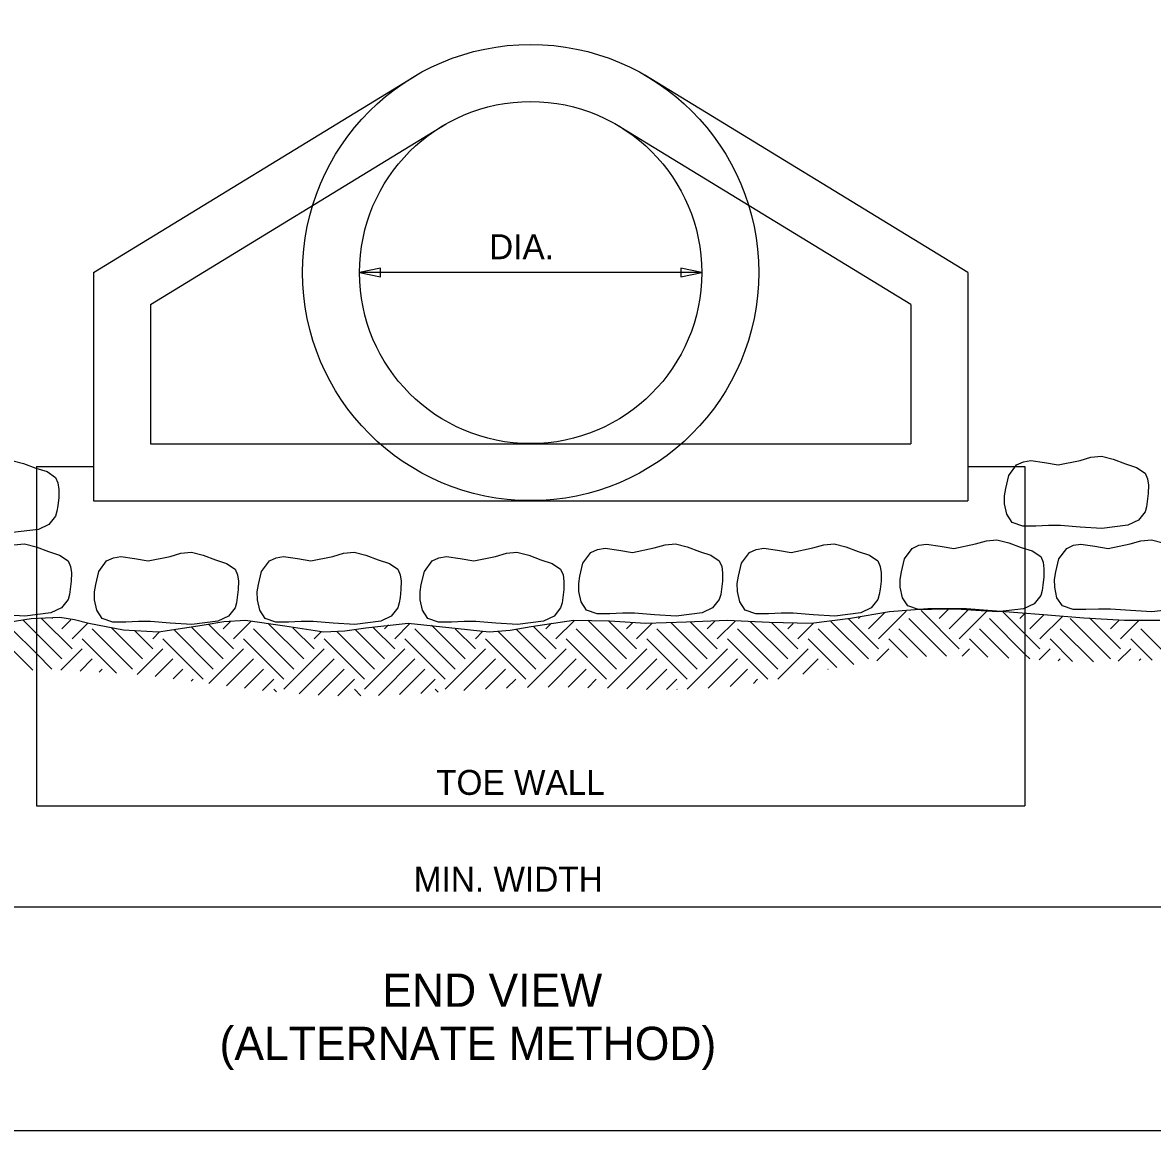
# Model space of a CAD drawing. Extents: x -439.1 to -407.9, y -458.1 to -436.2.
# Drawn here: x -431.65 to -424.86, y -458.05 to -451.39 of the extents above; entities that cross this region are included whole.
import ezdxf

# ---------------------------------------------------------------- set-up
doc = ezdxf.new("R2010")
doc.units = 0
doc.layers.add('Draft_Named_Boundary', color=7, linetype='Continuous')
doc.layers.add('Level 4', color=7, linetype='Continuous')

msp = doc.modelspace()

# ---------------------------------------------------------------- linework, layer by layer
at = {"layer": 'Draft_Named_Boundary'}
msp.add_lwpolyline([(-439.109, -458.0508), (-407.859, -458.0508), (-407.859, -437.6758), (-439.109, -437.6758)], close=True, dxfattribs=at)
at = {"layer": 'Level 4'}
for p, q in [((-431.2258, -452.893), (-429.2828, -451.7055)), ((-425.9682, -452.893), (-427.9112, -451.7055)), ((-430.8829, -453.0851), (-429.1045, -451.9981)), ((-426.3111, -453.0851), (-428.0907, -451.9981)), ((-431.2258, -452.893), (-431.2258, -454.2646)), ((-427.5687, -452.8928), (-429.626, -452.8928)), ((-425.9682, -452.893), (-425.9682, -454.2646)), ((-430.8829, -453.0851), (-430.8829, -453.9217)), ((-426.3111, -453.0851), (-426.3111, -453.9217)), ((-430.8829, -453.9217), (-426.3111, -453.9217)), ((-431.5687, -454.0588), (-431.2258, -454.0588)), ((-431.5687, -454.0588), (-431.5687, -456.1002)), ((-425.9682, -454.0588), (-425.6253, -454.0588)), ((-425.6253, -454.0588), (-425.6253, -456.1002)), ((-431.2258, -454.2646), (-425.9682, -454.2646)), ((-426.5659, -455.0344), (-426.4685, -454.9371)), ((-426.5053, -455.0951), (-426.339, -454.9288)), ((-426.0204, -455.1557), (-426.2505, -454.9256)), ((-426.1416, -454.9738), (-426.0874, -454.9196)), ((-426.081, -455.0344), (-425.9632, -454.9167)), ((-426.0204, -455.0951), (-425.8504, -454.925)), ((-425.6256, -455.0655), (-425.7594, -454.9318)), ((-425.6567, -454.9738), (-425.6256, -454.9428)), ((-425.6256, -454.9428), (-425.6246, -454.9417)), ((-425.5961, -455.0344), (-425.5117, -454.9501)), ((-425.5355, -455.0951), (-425.3986, -454.9582)), ((-431.569, -455.0623), (-431.6491, -454.9822)), ((-431.3544, -455.1557), (-431.5381, -454.972)), ((-431.4757, -454.9738), (-431.471, -454.9691)), ((-431.415, -455.0344), (-431.3612, -454.9806)), ((-431.3544, -455.0951), (-431.2602, -455.0008)), ((-430.4452, -455.2163), (-430.6353, -455.0262)), ((-430.3846, -455.1557), (-430.5334, -455.0069)), ((-430.4452, -455.0344), (-430.3993, -454.9886)), ((-430.3846, -455.0951), (-430.2777, -454.9882)), ((-429.9603, -455.2163), (-430.1766, -455)), ((-429.4148, -455.1557), (-429.5462, -455.0242)), ((-429.4754, -455.0344), (-429.4516, -455.0106)), ((-429.4148, -455.0951), (-429.3227, -455.003)), ((-428.9905, -455.2163), (-429.1937, -455.013)), ((-428.4449, -455.1557), (-428.5794, -455.0213)), ((-428.5056, -455.0344), (-428.4727, -455.0015)), ((-428.445, -455.0951), (-428.3346, -454.9847)), ((-428.0207, -455.2163), (-428.2537, -454.9832)), ((-427.96, -455.1557), (-428.1274, -454.9883)), ((-428.0207, -455.0344), (-427.9844, -454.9981)), ((-427.96, -455.0951), (-427.8668, -455.0018)), ((-427.5357, -455.2163), (-427.7527, -454.9994)), ((-427.4751, -455.1557), (-427.6376, -454.9932)), ((-427.5357, -455.0344), (-427.4877, -454.9864)), ((-427.4751, -455.0951), (-427.3666, -454.9865)), ((-427.0508, -455.2163), (-427.2771, -454.99)), ((-426.9902, -455.1557), (-427.1478, -454.9981)), ((-427.0508, -455.0344), (-427.0198, -455.0034)), ((-426.9902, -455.0951), (-426.896, -455.0008)), ((-426.5659, -455.2163), (-426.7917, -454.9905)), ((-426.5053, -455.1557), (-426.6871, -454.9739)), ((-426.6265, -454.9738), (-426.6138, -454.9611)), ((-426.098, -455.1993), (-426.3235, -454.9738)), ((-425.6256, -455.1867), (-425.8385, -454.9738)), ((-425.1112, -455.2163), (-425.3536, -454.9738)), ((-425.0506, -455.1557), (-425.2365, -454.9697)), ((-425.1112, -455.0344), (-425.0591, -454.9824)), ((-425.0506, -455.0951), (-424.9405, -454.985)), ((-431.569, -455.1836), (-431.7181, -455.0344)), ((-431.415, -455.2163), (-431.569, -455.0623)), ((-430.9907, -455.2769), (-431.2332, -455.0344)), ((-430.9301, -455.2163), (-431.1169, -455.0295)), ((-430.8695, -455.1557), (-430.9778, -455.0473)), ((-430.8695, -455.0951), (-430.8283, -455.0538)), ((-430.5058, -455.2769), (-430.7387, -455.044)), ((-430.0209, -455.2769), (-430.2634, -455.0344)), ((-429.8997, -455.1557), (-430.0265, -455.0289)), ((-429.8997, -455.0951), (-429.8574, -455.0527)), ((-429.536, -455.2769), (-429.762, -455.0509)), ((-429.4754, -455.2163), (-429.6519, -455.0398)), ((-429.0511, -455.2769), (-429.2935, -455.0344)), ((-428.9299, -455.1557), (-429.0515, -455.0341)), ((-428.9299, -455.0951), (-428.8866, -455.0518)), ((-428.5662, -455.2769), (-428.7925, -455.0505)), ((-428.5056, -455.2163), (-428.6829, -455.0389)), ((-428.0813, -455.2769), (-428.3237, -455.0344)), ((-427.5964, -455.2769), (-427.8388, -455.0344)), ((-427.1114, -455.2769), (-427.3539, -455.0344)), ((-426.6542, -455.2492), (-426.869, -455.0344)), ((-426.2175, -455.201), (-426.3841, -455.0344)), ((-425.7221, -455.2115), (-425.8992, -455.0344)), ((-425.5355, -455.1557), (-425.6256, -455.0655)), ((-425.2143, -455.2344), (-425.4142, -455.0344)), ((-424.7441, -455.2197), (-424.9293, -455.0344)), ((-431.5897, -455.284), (-431.7787, -455.0951)), ((-431.4217, -455.2836), (-431.2938, -455.1557)), ((-431.0866, -455.3023), (-431.2938, -455.0951)), ((-430.9632, -455.31), (-430.8089, -455.1557)), ((-430.5664, -455.3375), (-430.8089, -455.0951)), ((-430.5321, -455.3638), (-430.324, -455.1557)), ((-430.0815, -455.3375), (-430.324, -455.0951)), ((-430.0815, -455.3981), (-429.8391, -455.1557)), ((-429.5966, -455.3375), (-429.8391, -455.0951)), ((-429.5966, -455.3981), (-429.3542, -455.1557)), ((-429.1117, -455.3375), (-429.3542, -455.0951)), ((-429.1117, -455.3981), (-428.8692, -455.1557)), ((-428.6268, -455.3375), (-428.8692, -455.0951)), ((-428.6165, -455.3878), (-428.3843, -455.1557)), ((-428.1419, -455.3375), (-428.3843, -455.0951)), ((-428.1361, -455.3924), (-427.8994, -455.1557)), ((-427.657, -455.3375), (-427.8994, -455.0951)), ((-427.657, -455.3981), (-427.4145, -455.1557)), ((-427.1721, -455.3375), (-427.4145, -455.0951)), ((-427.1113, -455.3374), (-426.9296, -455.1557)), ((-426.7569, -455.2678), (-426.9296, -455.0951)), ((-426.5161, -455.2271), (-426.4447, -455.1557)), ((-426.3325, -455.2073), (-426.4447, -455.0951)), ((-426.0036, -455.1995), (-425.9598, -455.1557)), ((-425.8497, -455.2051), (-425.9598, -455.0951)), ((-425.5408, -455.2216), (-425.4749, -455.1557)), ((-425.3391, -455.2308), (-425.4749, -455.0951)), ((-425.0642, -455.2299), (-424.99, -455.1557)), ((-424.8613, -455.2237), (-424.99, -455.0951)), ((-431.4757, -455.2769), (-431.569, -455.1836)), ((-431.3056, -455.2887), (-431.2332, -455.2163)), ((-430.8543, -455.3223), (-430.7483, -455.2163)), ((-430.4256, -455.3785), (-430.2634, -455.2163)), ((-429.9889, -455.4268), (-429.7785, -455.2163)), ((-429.5124, -455.4351), (-429.2935, -455.2163)), ((-428.9988, -455.4064), (-428.8086, -455.2163)), ((-428.4927, -455.3852), (-428.3237, -455.2163)), ((-428.0186, -455.396), (-427.8388, -455.2163)), ((-427.5299, -455.3923), (-427.3539, -455.2163)), ((-426.9609, -455.3082), (-426.869, -455.2163)), ((-425.5961, -455.2163), (-425.6256, -455.1867)), ((-425.4258, -455.2278), (-425.4142, -455.2163)), ((-424.9391, -455.2261), (-424.9293, -455.2163)), ((-431.1915, -455.2958), (-431.1726, -455.2769)), ((-430.746, -455.3352), (-430.6877, -455.2769)), ((-430.3182, -455.3924), (-430.2028, -455.2769)), ((-429.8753, -455.4343), (-429.7178, -455.2769)), ((-429.3858, -455.4298), (-429.2329, -455.2769)), ((-428.8695, -455.3984), (-428.748, -455.2769)), ((-428.3726, -455.3864), (-428.2631, -455.2769)), ((-427.9001, -455.3988), (-427.7782, -455.2769)), ((-427.3978, -455.3814), (-427.2933, -455.2769)), ((-426.8097, -455.2782), (-426.8084, -455.2769)), ((-430.6389, -455.3494), (-430.6271, -455.3375)), ((-430.2104, -455.4057), (-430.1421, -455.3375)), ((-429.7569, -455.4371), (-429.6572, -455.3375)), ((-429.2578, -455.423), (-429.1723, -455.3375)), ((-428.7418, -455.3919), (-428.6874, -455.3375)), ((-428.2539, -455.3889), (-428.2025, -455.3375)), ((-427.7806, -455.4005), (-427.7176, -455.3375)), ((-427.2582, -455.363), (-427.2327, -455.3375)), ((-430.1257, -455.4146), (-430.1421, -455.3981)), ((-429.6178, -455.4376), (-429.6572, -455.3981)), ((-429.1541, -455.4164), (-429.1723, -455.3981)), ((-427.7163, -455.3994), (-427.7176, -455.3981)), ((-431.5687, -456.1002), (-425.6253, -456.1002)), ((-421.7848, -456.7088), (-435.0842, -456.7088))]:
    msp.add_line(p, q, dxfattribs=at)
for points in [[(-429.4995, -452.8666), (-429.626, -452.8928), (-429.4995, -452.9191)], [(-427.6951, -452.9191), (-427.5687, -452.8928), (-427.6951, -452.8666)], [(-425.7413, -454.1911), (-425.723, -454.1124), (-425.6756, -454.0498), (-425.6352, -454.0302), (-425.5902, -454.0235), (-425.5074, -454.0358), (-425.4259, -454.0498), (-425.2946, -454.0219), (-425.2296, -454.003), (-425.1663, -453.9972), (-425.0957, -454.0152), (-425.0217, -454.0432), (-424.9546, -454.0641), (-424.9034, -454.0991), (-424.8891, -454.1327), (-424.8837, -454.1713), (-424.8847, -454.221), (-424.8903, -454.2699), (-424.8951, -454.3021), (-424.9034, -454.3324), (-424.9434, -454.3823), (-425.0068, -454.4123), (-425.163, -454.4309), (-425.293, -454.4237), (-425.4127, -454.4145), (-425.4845, -454.4146), (-425.5606, -454.4178), (-425.6377, -454.4178), (-425.7019, -454.3948), (-425.7341, -454.3458), (-425.7479, -454.2831), (-425.7487, -454.2362), (-425.7413, -454.1911)], [(-428.3011, -454.7181), (-428.2828, -454.6395), (-428.2354, -454.5768), (-428.195, -454.5572), (-428.15, -454.5505), (-428.0672, -454.5628), (-427.9857, -454.5768), (-427.8544, -454.5489), (-427.7894, -454.5301), (-427.7261, -454.5242), (-427.6555, -454.5422), (-427.5815, -454.5702), (-427.5144, -454.5911), (-427.4632, -454.6261), (-427.4488, -454.6597), (-427.4435, -454.6984), (-427.4445, -454.748), (-427.4501, -454.7969), (-427.4549, -454.8292), (-427.4632, -454.8594), (-427.5032, -454.9093), (-427.5666, -454.9393), (-427.7228, -454.9579), (-427.8528, -454.9507), (-427.9725, -454.9415), (-428.0442, -454.9416), (-428.1204, -454.9448), (-428.1975, -454.9448), (-428.2617, -454.9218), (-428.2939, -454.8728), (-428.3077, -454.8101), (-428.3085, -454.7632), (-428.3011, -454.7181)], [(-427.3475, -454.7181), (-427.3291, -454.6395), (-427.2818, -454.5768), (-427.2414, -454.5572), (-427.1963, -454.5505), (-427.1135, -454.5628), (-427.032, -454.5768), (-426.9007, -454.5489), (-426.8357, -454.5301), (-426.7724, -454.5242), (-426.7019, -454.5422), (-426.6279, -454.5702), (-426.5607, -454.5911), (-426.5096, -454.6261), (-426.4952, -454.6597), (-426.4899, -454.6984), (-426.4909, -454.748), (-426.4964, -454.7969), (-426.5012, -454.8292), (-426.5096, -454.8594), (-426.5495, -454.9093), (-426.613, -454.9393), (-426.7692, -454.9579), (-426.8991, -454.9507), (-427.0189, -454.9415), (-427.0906, -454.9416), (-427.1668, -454.9448), (-427.2439, -454.9448), (-427.308, -454.9218), (-427.3403, -454.8728), (-427.354, -454.8101), (-427.3548, -454.7632), (-427.3475, -454.7181)], [(-426.3687, -454.693), (-426.3504, -454.6144), (-426.303, -454.5517), (-426.2626, -454.5321), (-426.2176, -454.5254), (-426.1348, -454.5377), (-426.0533, -454.5517), (-425.922, -454.5238), (-425.857, -454.505), (-425.7937, -454.4991), (-425.7231, -454.5171), (-425.6491, -454.5451), (-425.582, -454.566), (-425.5308, -454.601), (-425.5164, -454.6346), (-425.5111, -454.6733), (-425.5121, -454.7229), (-425.5177, -454.7718), (-425.5225, -454.8041), (-425.5308, -454.8343), (-425.5708, -454.8842), (-425.6342, -454.9142), (-425.7904, -454.9328), (-425.9204, -454.9256), (-426.0401, -454.9164), (-426.1119, -454.9165), (-426.188, -454.9197), (-426.2651, -454.9197), (-426.3293, -454.8967), (-426.3615, -454.8477), (-426.3753, -454.785), (-426.3761, -454.7381), (-426.3687, -454.693)], [(-431.2123, -454.7683), (-431.1939, -454.6897), (-431.1465, -454.627), (-431.1061, -454.6074), (-431.0611, -454.6007), (-430.9783, -454.613), (-430.8968, -454.627), (-430.7655, -454.5991), (-430.7005, -454.5803), (-430.6372, -454.5744), (-430.5666, -454.5924), (-430.4927, -454.6204), (-430.4255, -454.6413), (-430.3744, -454.6763), (-430.36, -454.7099), (-430.3546, -454.7486), (-430.3556, -454.7982), (-430.3612, -454.8471), (-430.366, -454.8793), (-430.3744, -454.9096), (-430.4143, -454.9595), (-430.4778, -454.9895), (-430.6339, -455.0081), (-430.7639, -455.0009), (-430.8837, -454.9917), (-430.9554, -454.9918), (-431.0315, -454.995), (-431.1086, -454.995), (-431.1728, -454.972), (-431.205, -454.923), (-431.2188, -454.8603), (-431.2196, -454.8134), (-431.2123, -454.7683)], [(-430.2335, -454.7683), (-430.2151, -454.6897), (-430.1678, -454.627), (-430.1274, -454.6074), (-430.0824, -454.6007), (-429.9996, -454.613), (-429.9181, -454.627), (-429.7868, -454.5991), (-429.7218, -454.5803), (-429.6585, -454.5744), (-429.5879, -454.5924), (-429.5139, -454.6204), (-429.4468, -454.6413), (-429.3956, -454.6763), (-429.3812, -454.7099), (-429.3759, -454.7486), (-429.3769, -454.7982), (-429.3825, -454.8471), (-429.3872, -454.8793), (-429.3956, -454.9096), (-429.4355, -454.9595), (-429.499, -454.9895), (-429.6552, -455.0081), (-429.7852, -455.0009), (-429.9049, -454.9917), (-429.9766, -454.9918), (-430.0528, -454.995), (-430.1299, -454.995), (-430.1941, -454.972), (-430.2263, -454.923), (-430.2401, -454.8603), (-430.2409, -454.8134), (-430.2335, -454.7683)], [(-429.2548, -454.7683), (-429.2364, -454.6897), (-429.1891, -454.627), (-429.1487, -454.6074), (-429.1036, -454.6007), (-429.0208, -454.613), (-428.9393, -454.627), (-428.808, -454.5991), (-428.743, -454.5803), (-428.6797, -454.5744), (-428.6092, -454.5924), (-428.5352, -454.6204), (-428.468, -454.6413), (-428.4169, -454.6763), (-428.4025, -454.7099), (-428.3972, -454.7486), (-428.3982, -454.7982), (-428.4037, -454.8471), (-428.4085, -454.8793), (-428.4169, -454.9096), (-428.4568, -454.9595), (-428.5203, -454.9895), (-428.6765, -455.0081), (-428.8064, -455.0009), (-428.9262, -454.9917), (-428.9979, -454.9918), (-429.0741, -454.995), (-429.1512, -454.995), (-429.2153, -454.972), (-429.2476, -454.923), (-429.2613, -454.8603), (-429.2621, -454.8134), (-429.2548, -454.7683)]]:
    msp.add_lwpolyline(points, close=True, dxfattribs=at)
for points in [[(-431.7163, -454.0223), (-431.6458, -454.0403), (-431.5718, -454.0683), (-431.5046, -454.0892), (-431.4535, -454.1242), (-431.4391, -454.1578), (-431.4338, -454.1964), (-431.4348, -454.2461), (-431.4403, -454.295), (-431.4451, -454.3272), (-431.4535, -454.3575), (-431.4934, -454.4073), (-431.5569, -454.4374), (-431.7131, -454.456)], [(-431.7043, -454.5301), (-431.6411, -454.5242), (-431.5705, -454.5422), (-431.4965, -454.5702), (-431.4294, -454.5911), (-431.3782, -454.6261), (-431.3638, -454.6597), (-431.3585, -454.6984), (-431.3595, -454.748), (-431.365, -454.7969), (-431.3698, -454.8292), (-431.3782, -454.8594), (-431.4181, -454.9093), (-431.4816, -454.9393), (-431.6378, -454.9579), (-431.7677, -454.9507)], [(-424.7057, -454.9142), (-424.8619, -454.9328), (-424.9918, -454.9256), (-425.1116, -454.9164), (-425.1833, -454.9165), (-425.2595, -454.9197), (-425.3366, -454.9197), (-425.4007, -454.8967), (-425.433, -454.8477), (-425.4468, -454.785), (-425.4476, -454.7381), (-425.4402, -454.693), (-425.4402, -454.693), (-425.4218, -454.6144), (-425.3745, -454.5517), (-425.3341, -454.5321), (-425.289, -454.5254), (-425.2062, -454.5377), (-425.1247, -454.5517), (-424.9934, -454.5238), (-424.9284, -454.505), (-424.8652, -454.4991), (-424.7946, -454.5171)], [(-424.8139, -454.9853), (-425.0262, -454.9848), (-425.2711, -454.9701), (-425.5145, -454.9499), (-425.9772, -454.9156), (-426.2087, -454.9141), (-426.439, -454.9324), (-426.6745, -454.9719), (-426.91, -455.0022), (-427.1624, -454.9974), (-427.4158, -454.9848), (-427.6601, -454.9945), (-427.9042, -455.0022), (-428.1225, -454.9885), (-428.3403, -454.9848), (-428.5935, -455.0239), (-428.7197, -455.0451), (-428.8461, -455.0545), (-429.09, -455.0284), (-429.3345, -455.0022), (-429.5877, -455.0306), (-429.7142, -455.0487), (-429.8404, -455.0545), (-430.076, -455.0193), (-430.3113, -454.9848), (-430.4419, -454.9923), (-430.5726, -455.0141), (-430.8346, -455.0545), (-431.0445, -455.044), (-431.2532, -455.0022), (-431.3405, -454.9814), (-431.4277, -454.9673), (-431.6008, -454.9746), (-431.7765, -455.0022)]]:
    msp.add_lwpolyline(points, dxfattribs=at)
for radius in [1.3715, 1.0287]:
    msp.add_circle((-428.5973, -452.8928), radius, dxfattribs=at)

# ---------------------------------------------------------------- texts
for s, height, p in [('DIA.', 0.15, (-428.8471, -452.8127)), ('TOE WALL', 0.15, (-429.1657, -456.0334)), ('MIN. WIDTH', 0.15, (-429.3001, -456.6154)), ('END VIEW', 0.2, (-429.4894, -457.3076)), ('(ALTERNATE METHOD)', 0.2, (-430.4678, -457.6276))]:
    msp.add_text(s, height=height, dxfattribs=at).set_placement(p)

doc.saveas('drawing.dxf')
